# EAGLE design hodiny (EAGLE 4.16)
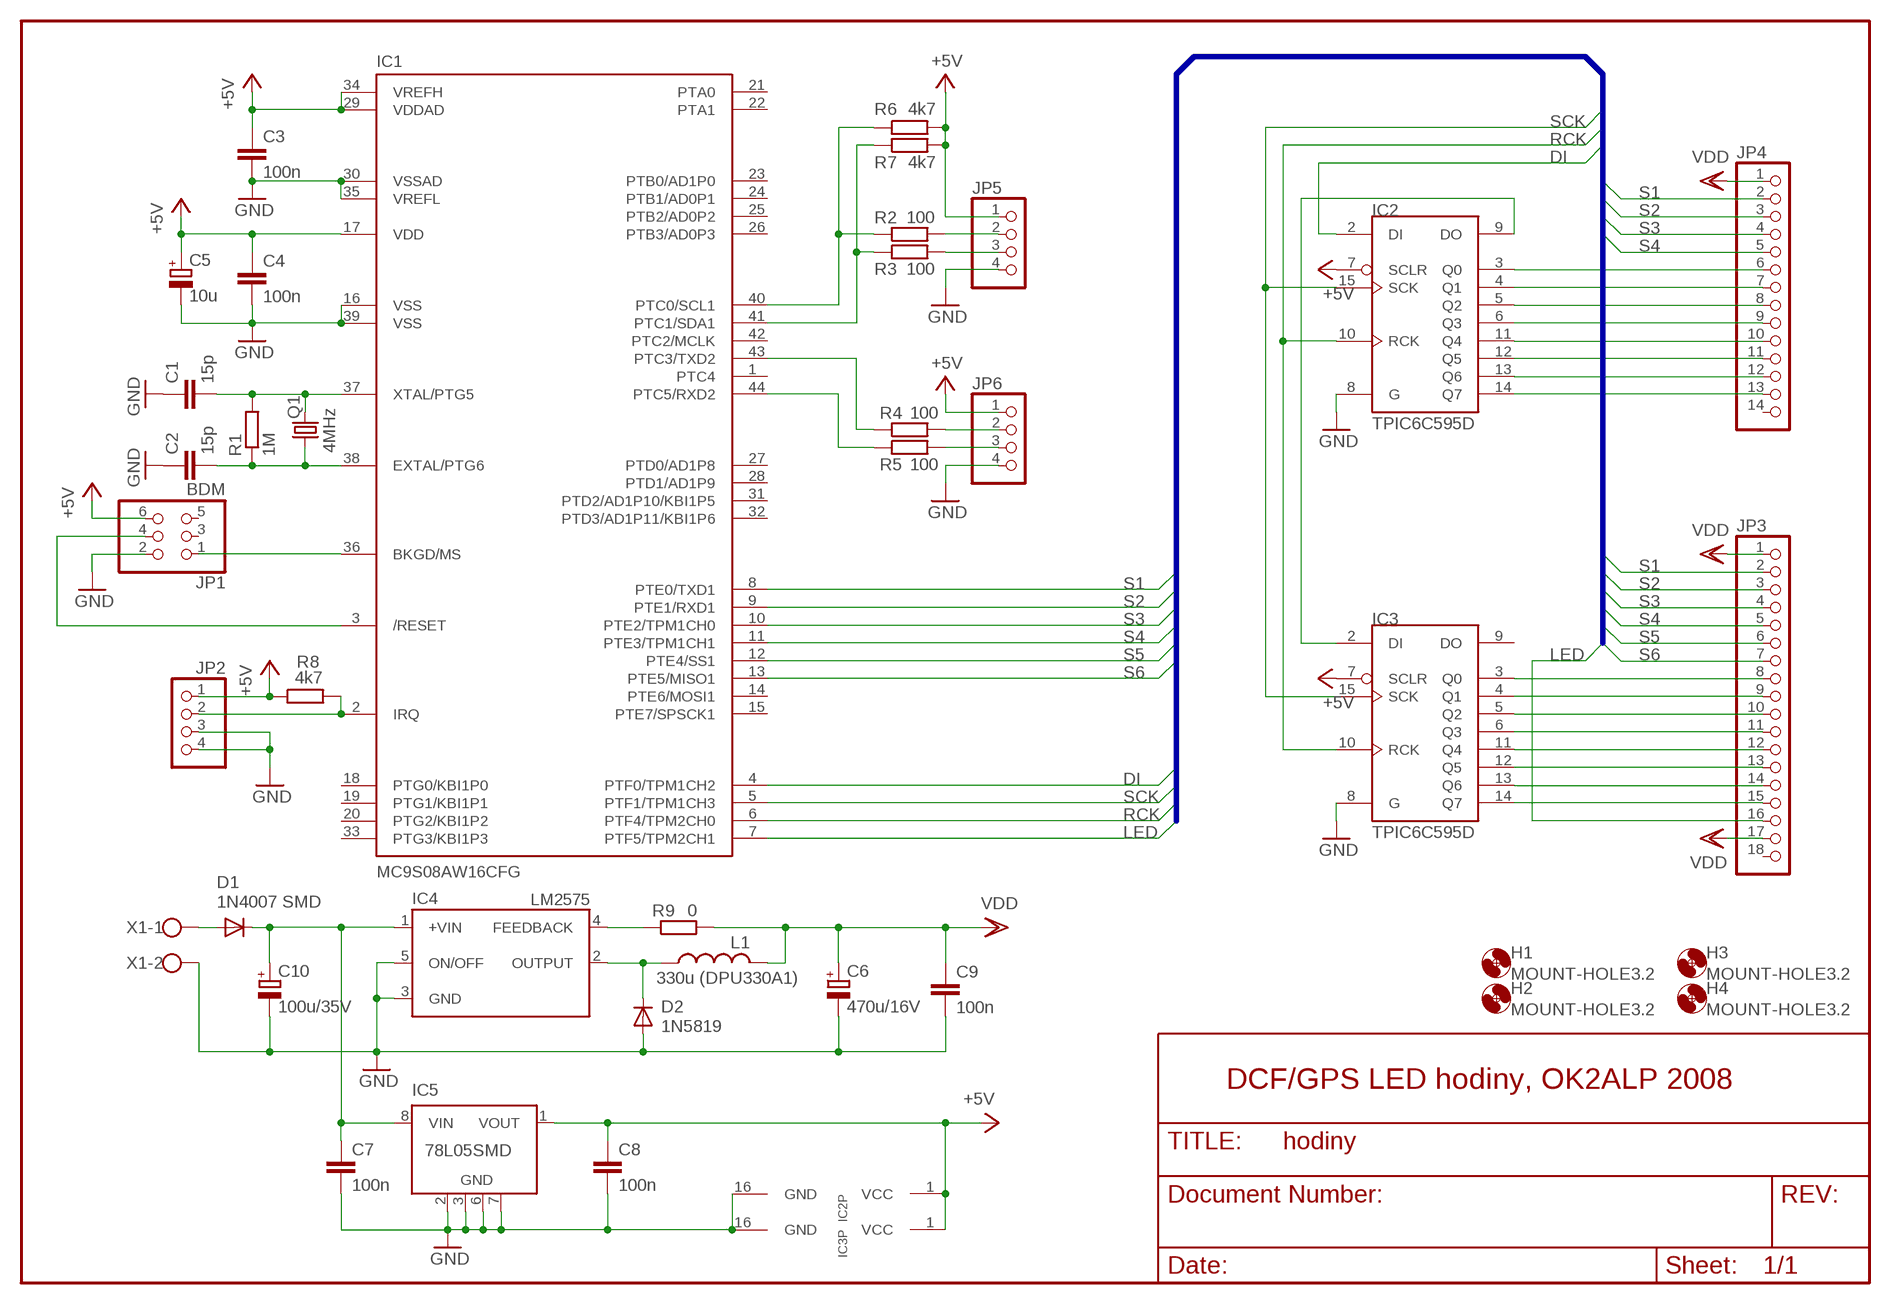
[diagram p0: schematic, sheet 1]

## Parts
C1  15p  C-EUC0805  [C0805]
C2  15p  C-EUC0805  [C0805]
C3  100n  C-EUC0805  [C0805]
C4  100n  C-EUC0805  [C0805]
C5  10u  CPOL-EUSMCB  [SMC_B]
C6  470u/16V  CPOL-EUE5-10.5  [E5-10,5]
C7  100n  C-EUC0805  [C0805]
C8  100n  C-EUC0805  [C0805]
C9  100n  C-EUC0805  [C0805]
C10  100u/35V  CPOL-EUE3.5-8  [E3,5-8]
D1  1N4007 SMD  DIODE-MELF-MLL41  [MELF-MLL41]
D2  1N5819  DIODE-DO35-10  [DO35-10]
H1  MOUNT-HOLE3.2  [3,2]
H2  MOUNT-HOLE3.2  [3,2]
H3  MOUNT-HOLE3.2  [3,2]
H4  MOUNT-HOLE3.2  [3,2]
IC1  MC9S08AW16CFG  [TQFP44]
IC2  TPIC6C595D  TPIC6C596PW  [SO16]
IC3  TPIC6C595D  TPIC6C596PW  [SO16]
IC4  LM2575  [TO220-5]
IC5  78L05SMD  [SO08]
JP1  BDM  PINHD-2X3P  [2X03P]
JP2  PINHD-1X4  [1X04]
JP3  PINHD-1X18  [1X18]
JP4  PINHD-1X14  [1X14]
JP5  PINHD-1X4  [1X04]
JP6  PINHD-1X4  [1X04]
L1  330u (DPU330A1)  L-USTJ4-U1  [TJ4-U1]
Q1  4MHz  CRYTALHC49S  [HC49/S]
R1  1M  R-EU_R0805  [R0805]
R2  100  R-EU_R0805  [R0805]
R3  100  R-EU_R0805  [R0805]
R4  100  R-EU_R0805  [R0805]
R5  100  R-EU_R0805  [R0805]
R6  4k7  R-EU_R0805  [R0805]
R7  4k7  R-EU_R0805  [R0805]
R8  4k7  R-EU_R0805  [R0805]
R9  0  R-EU_R0805  [R0805]
X1  W237-102  [W237-102]

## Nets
+5V: C3.1 C4.1 C5.+ C8.1 IC1.17(VDD) IC1.29(VDDAD) IC1.34(VREFH) IC2.1(VCC) IC2.7(SCLR) IC3.1(VCC) IC3.7(SCLR) IC5.1(VOUT) JP1.6 JP2.1 JP5.1 JP6.1 R6.2 R7.2 R8.1
DI: IC1.4(PTF0/TPM1CH2) IC2.2(DI)
GND: C1.1 C2.1 C3.2 C4.2 C5.- C6.- C7.2 C8.2 C9.2 C10.- D2.A IC1.16(VSS) IC1.30(VSSAD) IC1.35(VREFL) IC1.39(VSS) IC2.8(G) IC2.16(GND) IC3.8(G) IC3.16(GND) IC4.3(GND) IC4.5(ON/OFF) IC5.2(GND) IC5.3(GND) IC5.6(GND) IC5.7(GND) JP1.2 JP2.3 JP2.4 JP5.4 JP6.4 X1.2
LED: IC1.7(PTF5/TPM2CH1) JP3.16
N$1: C1.2 IC1.37(XTAL/PTG5) Q1.2 R1.2
N$2: C2.2 IC1.38(EXTAL/PTG6) Q1.1 R1.1
N$3: IC1.36(BKGD/MS) JP1.1
N$4: IC1.3(/RESET) JP1.4
N$5: IC2.9(DO) IC3.2(DI)
N$6: D1.A X1.1
N$7: D2.C IC4.2(OUTPUT) L1.1
N$8: JP5.3 R3.2
N$9: JP5.2 R2.2
N$10: JP6.2 R4.2
N$11: JP6.3 R5.2
N$12: IC1.40(PTC0/SCL1) R2.1 R6.1
N$13: IC1.2(IRQ) JP2.2 R8.2
N$14: IC1.41(PTC1/SDA1) R3.1 R7.1
N$15: IC1.43(PTC3/TXD2) R4.1
N$16: IC1.44(PTC5/RXD2) R5.1
N$17: IC4.4(FEEDBACK) R9.1
N$18: IC3.3(Q0) JP3.8
N$19: IC3.4(Q1) JP3.9
N$20: IC3.5(Q2) JP3.10
N$21: IC3.6(Q3) JP3.11
N$22: IC3.11(Q4) JP3.12
N$23: IC3.12(Q5) JP3.13
N$24: IC3.13(Q6) JP3.14
N$25: IC3.14(Q7) JP3.15
N$27: IC2.3(Q0) JP4.6
N$28: IC2.4(Q1) JP4.7
N$29: IC2.5(Q2) JP4.8
N$30: IC2.6(Q3) JP4.9
N$31: IC2.11(Q4) JP4.10
N$32: IC2.12(Q5) JP4.11
N$33: IC2.13(Q6) JP4.12
N$34: IC2.14(Q7) JP4.13
N$35: C7.1 C10.+ D1.C IC4.1(+VIN) IC5.8(VIN)
RCK: IC1.6(PTF4/TPM2CH0) IC2.10(RCK) IC3.10(RCK)
S1: IC1.8(PTE0/TXD1) JP3.2 JP4.2
S2: IC1.9(PTE1/RXD1) JP3.3 JP4.3
S3: IC1.10(PTE2/TPM1CH0) JP3.4 JP4.4
S4: IC1.11(PTE3/TPM1CH1) JP3.5 JP4.5
S5: IC1.12(PTE4/SS1) JP3.6
S6: IC1.13(PTE5/MISO1) JP3.7
SCK: IC1.5(PTF1/TPM1CH3) IC2.15(SCK) IC3.15(SCK)
VDD: C6.+ C9.1 JP3.1 JP3.17 JP4.1 L1.2 R9.2
Unconnected: IC1.1(PTC4) IC1.14(PTE6/MOSI1) IC1.15(PTE7/SPSCK1) IC1.18(PTG0/KBI1P0) IC1.19(PTG1/KBI1P1) IC1.20(PTG2/KBI1P2) IC1.21(PTA0) IC1.22(PTA1) IC1.23(PTB0/AD1P0) IC1.24(PTB1/AD0P1) IC1.25(PTB2/AD0P2) IC1.26(PTB3/AD0P3) IC1.27(PTD0/AD1P8) IC1.28(PTD1/AD1P9) IC1.31(PTD2/AD1P10/KBI1P5) IC1.32(PTD3/AD1P11/KBI1P6) IC1.33(PTG3/KBI1P3) IC1.42(PTC2/MCLK) IC3.9(DO) IC5.4(NC) IC5.5(NC) JP1.3 JP1.5 JP3.18 JP4.14

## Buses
S[1..6],LED,DI,SCK,RCK

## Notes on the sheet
- DCF/GPS LED hodiny, OK2ALP 2008

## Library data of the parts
C1-C4 C7-C9 = rcl:C-EU: CAPACITOR, European symbol
C5 C6 C10 = rcl:CPOL-EU: POLARIZED CAPACITOR, European symbol
D1 D2 = diode:DIODE-: DIODE
H1-H4 = holes:MOUNT-HOLE: MOUNTING HOLE with drill center marker
IC1 = alpov:MC9S08AW16CFG
IC2 IC3 = tpic:TPIC6C596
IC4 = alpov:LM2575
IC5 = linear:78L*SMD: Positive VOLTAGE REGULATOR
JP1 = pinhead:PINHD-2X3: PIN HEADER
JP2 JP5 JP6 = pinhead:PINHD-1X4: PIN HEADER
JP3 = pinhead:PINHD-1X18: PIN HEADER
JP4 = pinhead:PINHD-1X14: PIN HEADER
L1 = rcl:L-US: INDUCTOR, American symbol
Q1 = crystal:CRYTAL: CRYSTAL
R1-R9 = rcl:R-EU_: RESISTOR, European symbol
X1 = con-wago-500:W237-102: WAGO SCREW CLAMP

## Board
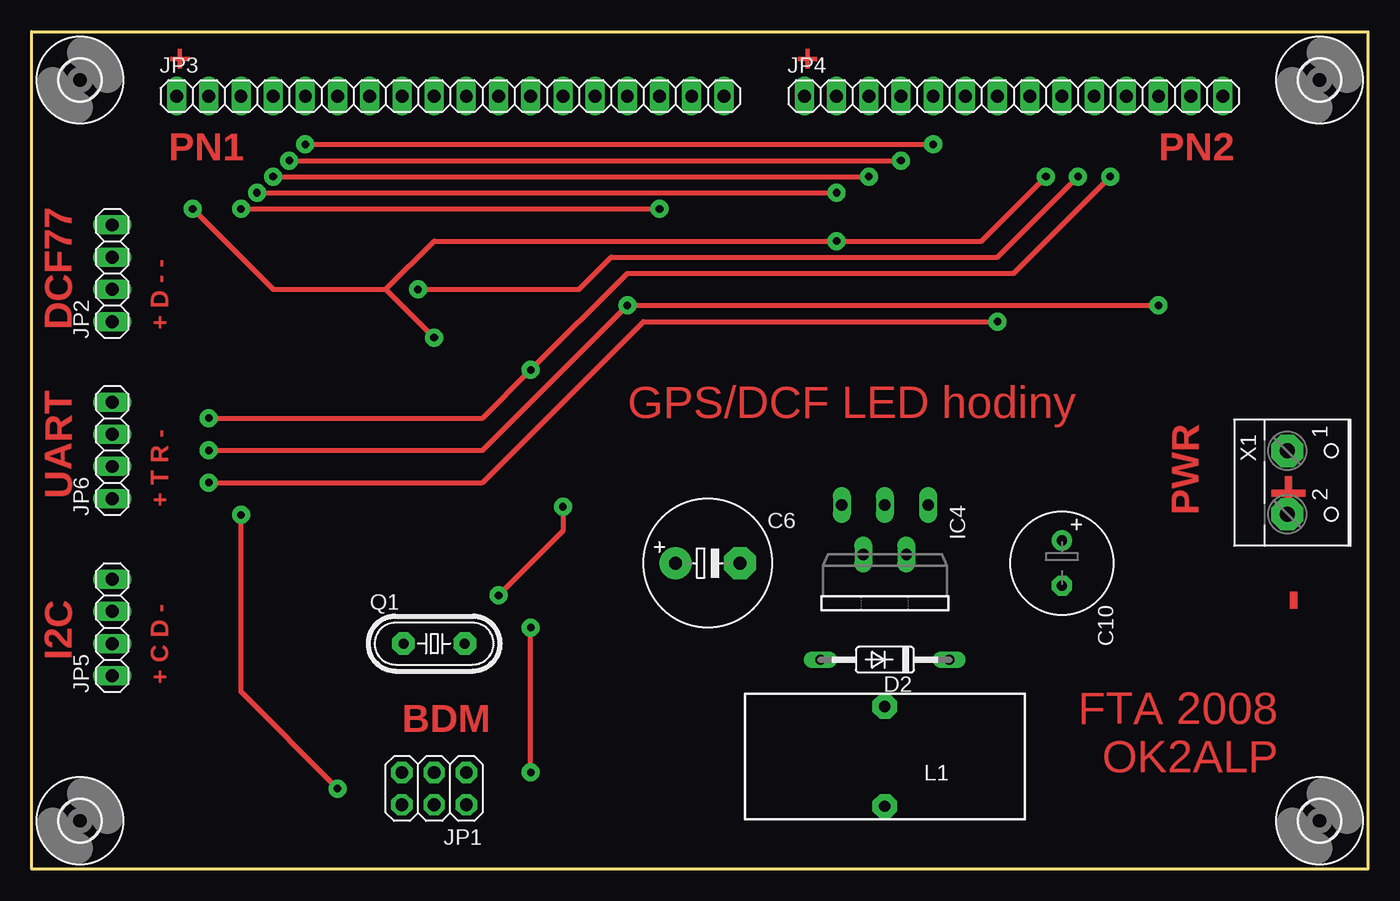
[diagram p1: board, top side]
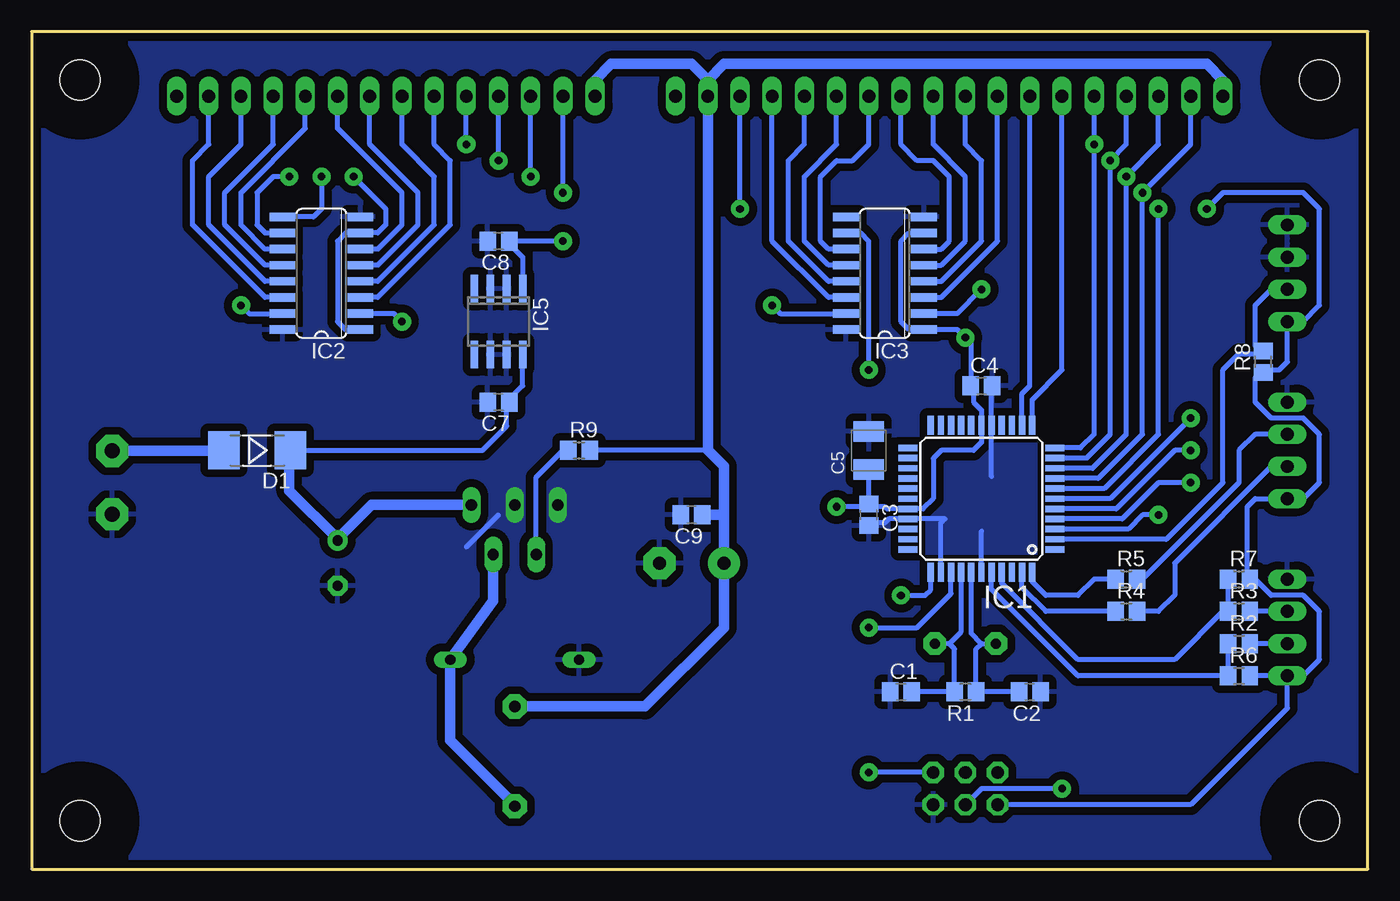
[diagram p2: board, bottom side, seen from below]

Size 105.41 x 66.04 mm. Coordinates in mm from the lower left corner, seen from the top.
Outline: 0,0 0,66.04 105.41,66.04 105.41,0 0,0
Copper layers (1*16): Top 0.035mm / dielectric 1.5mm / Bottom 0.035mm
Design rules "default": minimum track width 10mil, minimum drill 24mil, track to track 8mil, track to pad 8mil, pad to pad 8mil, via to via 8mil, smd to smd 8mil, copper to edge 20mil, drill to drill 8mil, minimum pad ring 10mil, minimum via ring 8mil, stop-mask expansion 4mil, vias tented up to drill 0mil, thermal gap 24mil

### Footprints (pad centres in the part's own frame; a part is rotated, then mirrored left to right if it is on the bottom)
C0805 = smd 1.3 x 1.5: 1 -0.85,0; 2 0.85,0
SMC_B = smd 1.6 x 2.4: + -1.5,0; - 1.5,0
E5-10,5 = drill 1.016 pad 2.54 round: + -2.54,0 | drill 1.016 pad 2.54 octagon: - 2.54,0
E3,5-8 = drill 0.813 pad 1.6 round: + -1.778,0 | drill 0.813 pad 1.6 octagon: - 1.778,0
MELF-MLL41 = smd 2.5 x 3: A 2.625,0; C -2.625,0
DO35-10 = drill 0.813 long: A 5.08,0; C -5.08,0
3,2 = hole 3.2: 0,0
TQFP44 = smd 1.5 x 0.5: 1 -5.8,4; 2 -5.8,3.2; 3 -5.8,2.4; 4 -5.8,1.6; 5 -5.8,0.8; 6 -5.8,0; 7 -5.8,-0.8; 8 -5.8,-1.6; 9 -5.8,-2.4; 10 -5.8,-3.2; 11 -5.8,-4; 23 5.8,-4; 24 5.8,-3.2; 25 5.8,-2.4; 26 5.8,-1.6; 27 5.8,-0.8; 28 5.8,0; 29 5.8,0.8; 30 5.8,1.6; 31 5.8,2.4; 32 5.8,3.2; 33 5.8,4 | smd 0.5 x 1.5: 12 -4,-5.8; 13 -3.2,-5.8; 14 -2.4,-5.8; 15 -1.6,-5.8; 16 -0.8,-5.8; 17 0,-5.8; 18 0.8,-5.8; 19 1.6,-5.8; 20 2.4,-5.8; 21 3.2,-5.8; 22 4,-5.8; 34 4,5.8; 35 3.2,5.8; 36 2.4,5.8; 37 1.6,5.8; 38 0.8,5.8; 39 0,5.8; 40 -0.8,5.8; 41 -1.6,5.8; 42 -2.4,5.8; 43 -3.2,5.8; 44 -4,5.8
SO16 = smd 0.66 x 2.032: 1 -4.445,-3.073; 2 -3.175,-3.073; 3 -1.905,-3.073; 4 -0.635,-3.073; 5 0.635,-3.073; 6 1.905,-3.073; 7 3.175,-3.073; 8 4.445,-3.073; 9 4.445,3.073; 10 3.175,3.073; 11 1.905,3.073; 12 0.635,3.073; 13 -0.635,3.073; 14 -1.905,3.073; 15 -3.175,3.073; 16 -4.445,3.073
TO220-5 = drill 0.9 long: 1 -3.4,-8.4; 2 -1.7,-4.5; 3 0,-8.4; 4 1.7,-4.5; 5 3.4,-8.4
SO08 = smd 0.6 x 2.2: 1 -1.905,-2.6; 2 -0.635,-2.6; 3 0.635,-2.6; 4 1.905,-2.6; 5 1.905,2.6; 6 0.635,2.6; 7 -0.635,2.6; 8 -1.905,2.6
2X03P = drill 1 pad 1.676 octagon: 1 -2.54,-1.27; 2 -2.54,1.27; 3 0,-1.27; 4 0,1.27; 5 2.54,-1.27; 6 2.54,1.27
1X04 = drill 1.016 long: 1 -3.81,0; 2 -1.27,0; 3 1.27,0; 4 3.81,0
1X18 = drill 1.016 long: 1 -21.59,0; 2 -19.05,0; 3 -16.51,0; 4 -13.97,0; 5 -11.43,0; 6 -8.89,0; 7 -6.35,0; 8 -3.81,0; 9 -1.27,0; 10 1.27,0; 11 3.81,0; 12 6.35,0; 13 8.89,0; 14 11.43,0; 15 13.97,0; 16 16.51,0; 17 19.05,0; 18 21.59,0
1X14 = drill 1.016 long: 1 -16.51,0; 2 -13.97,0; 3 -11.43,0; 4 -8.89,0; 5 -6.35,0; 6 -3.81,0; 7 -1.27,0; 8 1.27,0; 9 3.81,0; 10 6.35,0; 11 8.89,0; 12 11.43,0; 13 13.97,0; 14 16.51,0
TJ4-U1 = drill 0.9 pad 1.93 octagon: 1 -3.935,0; 2 3.935,0
HC49/S = drill 0.8 pad 1.778 octagon: 1 -2.413,0; 2 2.413,0
R0805 = smd 1.3 x 1.5: 1 -0.85,0; 2 0.85,0
W237-102 = drill 1.194 pad 2.54 octagon: 1 -2.5,-1.27; 2 2.5,-1.27

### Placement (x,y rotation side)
C1  36.83,13.97 0 bottom
C2  26.67,13.97 180 bottom
C3  39.37,27.94 270 bottom
C4  30.48,38.1 0 bottom
C5  39.37,33.02 90 bottom
C6  53.34,24.13 0 top
C7  68.58,36.83 180 bottom
C8  68.58,49.53 180 bottom
C9  53.34,27.94 180 bottom
C10  81.28,24.13 270 top
D1  87.63,33.02 180 bottom
D2  67.31,16.51 180 top
H1  3.81,62.23 0 top
H2  101.6,62.23 0 top
H3  101.6,3.81 0 top
H4  3.81,3.81 0 top
IC1  30.48,29.21 180 bottom
IC2  82.55,46.99 90 bottom
IC3  38.1,46.99 90 bottom
IC4  67.31,20.32 180 top
IC5  68.58,43.18 180 bottom
JP1  31.75,6.35 180 top
JP2  6.35,46.99 90 top
JP3  33.02,60.96 0 top
JP4  77.47,60.96 0 top
JP5  6.35,19.05 90 top
JP6  6.35,33.02 90 top
L1  67.31,8.89 90 top
Q1  31.75,17.78 0 top
R1  31.75,13.97 180 bottom
R2  10.16,17.78 0 bottom
R3  10.16,20.32 0 bottom
R4  19.05,20.32 0 bottom
R5  19.05,22.86 0 bottom
R6  10.16,15.24 0 bottom
R7  10.16,22.86 0 bottom
R8  8.26,40.01 90 bottom
R9  62.23,33.02 0 bottom
X1  100.33,30.48 270 top

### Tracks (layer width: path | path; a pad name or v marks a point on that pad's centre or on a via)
+5V  (via drill 0.6 pad 1.42)
  Top 0.406: 27.94,45.72 19.05,45.72 v12.7,52.07 | 27.94,45.72 v31.75,41.91 | 27.94,45.72 31.75,49.53 v63.5,49.53 74.93,49.53 v80.01,54.61 | v41.91,28.57 41.91,26.67 v36.83,21.59
  Bottom 0.406: 67.94,49.53 C8.1 | IC5.1 66.67,48.26 67.94,49.53 | 39.37,28.57 38.1,28.57 37.94,28.41 IC1.29 35.09,28.41 34.29,29.21 34.29,32.38 33.66,33.02 31.11,33.02 30.48,33.66 IC1.17 30.48,36.2 31.11,36.83 31.11,38.1 C4.1 31.33,41.49 v31.75,41.91 32.38,42.55 IC3.1 36.2,42.55 36.83,43.18 36.83,49.53 36.2,50.16 IC3.7 | IC2.1 80.64,42.55 81.28,43.18 81.28,49.53 80.64,50.16 79.38,50.16 | JP5.1 5.08,15.24 3.81,16.51 3.81,20.32 5.08,21.59 7.62,21.59 8.89,22.86 R7.2 9.53,22.86 9.53,28.57 8.89,29.21 JP6.1 5.08,29.21 3.81,30.48 3.81,34.29 5.08,35.56 7.62,35.56 8.89,36.83 8.89,38.73 8.26,39.37 | JP5.1 R6.2 | 39.37,28.57 C3.1 C5.+ 39.37,31.75 | 8.26,39.37 R8.1 | 8.26,39.37 6.99,39.37 6.35,40.01 JP2.1 5.08,43.18 3.81,44.45 3.81,52.07 5.08,53.34 11.43,53.34 v12.7,52.07 | 79.38,50.16 78.11,50.16 77.47,50.8 77.47,52.07 v80.01,54.61 | 79.38,50.16 IC2.7 | v63.5,49.53 67.94,49.53 | 39.37,28.57 v41.91,28.57 | IC1.34 34.48,22.04 34.92,21.59 v36.83,21.59 | JP1.6 13.97,5.08 6.35,12.7 JP5.1
DI  (via drill 0.6 pad 1.42)
  Top 0.406: v13.97,30.48 35.56,30.48 48.26,43.18 v76.2,43.18
  Bottom 0.406: IC1.4 19.38,27.61 16.51,30.48 v13.97,30.48 | v76.2,43.18 76.83,43.81 IC2.2
GND
  Bottom 0.406: C4.2 29.21,38.1 29.68,37.63 IC1.16 29.68,30.95 | C3.2 39.37,27.3 38.1,27.3 37.8,27.61 IC1.30 33.35,27.61 33.68,27.28 IC1.35 | IC1.39 30.48,26.67 | 68.58,27.94 71.12,25.4
  pour Bottom (isolate 0.61): 0,66.04 0,0 105.41,0 105.41,66.04
  pour Bottom (isolate 0.61, no thermals): 62.23,31.11 62.23,22.23 72.39,22.23 72.39,31.11
LED  (via drill 0.6 pad 1.42)
  Top 0.406: v16.51,52.07 v49.53,52.07
  Bottom 0.406: v49.53,52.07 JP3.16 | IC1.7 20.79,30.01 16.51,34.29 v16.51,52.07
N$1
  Bottom 0.406: IC1.37 32.08,18.72 33.02,17.78 | 33.02,17.78 Q1.2 | 33.02,17.78 32.6,17.36 R1.2 C1.2
N$2
  Bottom 0.406: IC1.38 31.28,18.58 30.48,17.78 | 30.48,17.78 Q1.1 | 30.48,17.78 30.9,17.36 R1.1 C2.2
N$3  (via drill 0.6 pad 1.42)
  Top 0.406: v39.37,7.62 v39.37,19.05
  Bottom 0.406: IC1.36 32.88,21.73 35.56,19.05 v39.37,19.05 | JP1.1 v39.37,7.62
N$4  (via drill 0.6 pad 1.42)
  Top 0.406: v16.51,27.94 16.51,13.97 v24.13,6.35
  Bottom 0.406: IC1.3 18.91,26.81 17.78,27.94 v16.51,27.94 | v24.13,6.35 30.48,6.35 JP1.4
N$5  (via drill 0.6 pad 1.42)
  Top 0.406: v30.48,45.72 43.18,45.72 45.72,48.26 76.2,48.26 v82.55,54.61
  Bottom 0.406: IC3.2 32.38,43.81 v30.48,45.72 | v82.55,54.61 82.55,52.07 83.19,51.44 IC2.9 85.72,51.44
N$6
  Bottom 0.813: D1.A 90.17,33.02 90.21,32.98 X1.1
N$7
  Bottom 0.813: IC4.2 69.01,21.16 D2.C 72.39,10.16 67.31,5.08 L1.1
N$8
  Bottom 0.406: JP5.3 R3.2
N$9
  Bottom 0.406: JP5.2 R2.2
N$10
  Bottom 0.406: R4.2 16.51,20.32 15.24,21.59 15.24,24.13 7.62,31.75 JP6.2
N$11
  Bottom 0.406: R5.2 17.78,22.86 10.16,30.48 10.16,33.02 8.89,34.29 JP6.3
N$12
  Bottom 0.406: R2.1 11.01,15.46 10.79,15.24 R6.1 22.86,15.24 29.68,22.06 IC1.40
N$13
  Bottom 0.406: IC1.2 15.9,26.01 11.43,30.48 11.43,39.37 10.16,40.64 8.26,40.64 | 8.26,40.64 R8.2 | 8.26,40.64 8.89,41.27 8.89,44.45 7.62,45.72 JP2.2
N$14
  Bottom 0.406: R7.1 11.01,20.54 10.79,20.32 R3.1 11.43,20.32 15.24,16.51 22.86,16.51 28.88,22.53 IC1.41
N$15
  Bottom 0.406: IC1.43 27.28,22.2 25.4,20.32 R4.1
N$16
  Bottom 0.406: IC1.44 26.48,22.67 25.4,21.59 22.86,21.59 21.59,22.86 R5.1
N$17
  Bottom 0.406: R9.1 63.5,33.02 65.61,30.91 IC4.4
N$18
  Bottom 0.406: IC3.3 33.66,45.09 29.21,49.53 JP3.8
N$19
  Bottom 0.406: IC3.4 33.66,46.35 30.48,49.53 30.48,55.88 31.75,57.15 JP3.9
N$20
  Bottom 0.406: IC3.5 33.66,47.62 31.75,49.53 31.75,54.61 34.29,57.15 JP3.10
N$21
  Bottom 0.406: IC3.6 33.66,48.9 33.02,49.53 33.02,54.61 34.29,55.88 35.56,55.88 36.83,57.15 JP3.11
N$22
  Bottom 0.406: IC3.11 42.55,48.9 43.18,49.53 43.18,54.61 41.91,55.88 40.64,55.88 39.37,57.15 JP3.12
N$23
  Bottom 0.406: IC3.12 42.55,47.62 44.45,49.53 44.45,54.61 41.91,57.15 JP3.13
N$24
  Bottom 0.406: IC3.13 42.55,46.35 45.72,49.53 45.72,55.88 44.45,57.15 JP3.14
N$25
  Bottom 0.406: IC3.14 42.55,45.09 46.99,49.53 JP3.15
N$27
  Bottom 0.406: IC2.3 78.11,45.09 72.39,50.8 72.39,55.88 73.66,57.15 JP4.6
N$28
  Bottom 0.406: IC2.4 78.11,46.35 73.66,50.8 73.66,54.61 76.2,57.15 JP4.7
N$29
  Bottom 0.406: IC2.5 78.11,47.62 74.93,50.8 74.93,53.34 78.74,57.15 JP4.8
N$30
  Bottom 0.406: IC2.6 78.11,48.9 76.2,50.8 76.2,53.34 81.28,58.42 JP4.9
N$31
  Bottom 0.406: IC2.11 87,48.9 88.9,50.8 88.9,53.34 83.82,58.42 JP4.10
N$32
  Bottom 0.406: IC2.12 87,47.62 90.17,50.8 90.17,53.34 86.36,57.15 JP4.11
N$33
  Bottom 0.406: IC2.13 87,46.35 91.44,50.8 91.44,54.61 88.9,57.15 JP4.12
N$34
  Bottom 0.406: IC2.14 87,45.09 92.71,50.8 92.71,55.88 91.44,57.15 JP4.13
N$35
  Bottom 0.406: IC5.8 66.67,38.1 67.94,36.83 | 67.94,36.83 C7.1 | 67.94,36.83 67.94,34.92 69.85,33.02 85.09,33.02
  Bottom 0.813: IC4.1 78.59,28.72 81.28,26.04 | D1.C 85.09,33.02 85.09,29.84 81.28,26.04 | 81.28,26.04 C10.+
RCK  (via drill 0.6 pad 1.42)
  Top 0.406: v85.09,54.61 77.47,46.99 46.99,46.99 v39.37,39.37 35.56,35.56 v13.97,35.56
  Bottom 0.406: IC3.10 40.01,50.16 39.37,49.53 v39.37,39.37 | IC2.10 87,50.16 87.63,50.8 87.63,53.34 86.36,54.61 v85.09,54.61 | IC1.6 20.32,29.21 v13.97,35.56
S1  (via drill 0.6 pad 1.42)
  Top 0.406: v17.78,53.34 v63.5,53.34
  Bottom 0.406: IC1.8 21.26,30.81 17.78,34.29 v17.78,53.34 13.97,57.15 JP3.2 | v63.5,53.34 JP4.2
S2  (via drill 0.6 pad 1.42)
  Top 0.406: v19.05,54.61 v66.04,54.61
  Bottom 0.406: IC1.9 21.73,31.61 19.05,34.29 v19.05,54.61 16.51,57.15 JP3.3 | v66.04,54.61 JP4.3
S3  (via drill 0.6 pad 1.42)
  Top 0.406: v20.32,55.88 v68.58,55.88
  Bottom 0.406: IC1.10 22.2,32.41 20.32,34.29 v20.32,55.88 19.05,57.15 JP3.4 | v68.58,55.88 JP4.4
S4  (via drill 0.6 pad 1.42)
  Top 0.406: v21.59,57.15 v71.12,57.15
  Bottom 0.406: IC1.11 22.67,33.21 21.59,34.29 v21.59,57.15 JP3.5 | v71.12,57.15 JP4.5
S5
  Bottom 0.406: IC1.12 26.48,37.02 24.13,39.37 JP3.6
S6
  Bottom 0.406: IC1.13 27.28,37.49 26.67,38.1 JP3.7
SCK  (via drill 0.6 pad 1.42)
  Top 0.406: v88.9,44.45 v46.99,44.45 35.56,33.02 v13.97,33.02
  Bottom 0.406: IC3.15 46.35,43.81 v46.99,44.45 | IC2.15 88.27,43.81 v88.9,44.45 | IC1.5 19.85,28.41 15.24,33.02 v13.97,33.02
VDD
  Bottom 0.406: 52.07,33.02 R9.2
  Bottom 0.813: JP3.1 11.43,62.23 12.7,63.5 50.8,63.5 52.07,62.23 | 52.07,62.23 JP3.17 52.07,33.02 50.8,31.75 50.8,27.94 | JP4.1 60.96,62.23 59.69,63.5 53.34,63.5 52.07,62.23 | L1.2 57.02,12.82 50.8,19.05 C6.+ 50.8,27.94 | 50.8,27.94 C9.1

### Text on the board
Top: + | + | PN1 | PN2 | DCF77 | + D - - | GPS/DCF LED hodiny | UART | + T R - | PWR | - + | I2C | + C D - | BDM | FTA 2008 | OK2ALP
